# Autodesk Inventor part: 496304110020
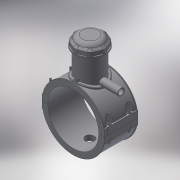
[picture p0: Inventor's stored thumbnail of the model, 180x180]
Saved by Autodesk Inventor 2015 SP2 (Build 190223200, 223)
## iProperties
Created: 2017-07
Part Number: 496304110020
Material: Generic
Description: PLASSON TAPPING SADDLE 110x20
Document SubType Name: Modeling
Designer: KIM
Mass: 688.812 g
Surface Area: 1656.06 cm^2
Volume: 688.812 cm^3
Density: 1 g/cm^3
Appearance: Default
Author: KIM
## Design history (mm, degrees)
derived "496304.ipt"
feature "Solid1::496304.ipt"
feature "Solid2::496304.ipt"
feature "Solid4::496304.ipt"
feature "Solid5::496304.ipt"
tag "TaggingFeature1"
body "Solid1"
body "Solid2"
other parameters: "d2" = 148, "d3" = 27.5, "d4" = 118, "d5" = 0, "d6" = 0.1, "d8" = 0, "d19" = 6, "d20" = 6, "d21" = 70.8, "d23" = 0, "d24" = 35.4, "d26" = 0, "d29" = 3, "d30" = 36.66667, "d31" = 6, "d32" = 0, "d33" = 0, "d34" = 0.6, "d40" = 68.64, "d41" = 66, "d43" = 0, "d45" = 0, "d47" = 136.8, "d70" = 15, "d72" = 0, "d73" = 6, "d75" = 5, "d76" = 0, "d77" = 5.5, "d78" = 85, "d79" = 15, "d80" = 47.2, "d82" = 5 deg, "d84" = 4, "d85" = 14, "d86" = 0, "d87" = 3, "d88" = 0, "d89" = 1, "d90" = 1, "d91" = 94.4, "d92" = 0, "d93" = 0.5, "d94" = 57.89474, "d96" = 134.64, "d97" = 2.36, "d98" = 0, "d102" = 1.1, "d120" = 140 deg, "d121" = 24.228, "d122" = 20 deg, "d123" = 264, "d124" = 79.2, "d126" = 0, "d143" = 113.3, "d145" = 16.92308, "d149" = 1.65, "d150" = 18.61538, "d153" = 118, "d154" = 0, "d156" = 66, "d157" = 160 deg, "d159" = 4.4, "d161" = 1.65, "d162" = 70.8, "d163" = 0, "d164" = 55, "d167" = 11, "d168" = 64.39024, "d170" = 3.375, "d172" = 0, "d173" = 1, "d175" = 55, "d176" = 20 deg, "d177" = 7.7, "d178" = 22, "d180" = 0, "d183" = 8.8, "d184" = 6.16, "d185" = 38.35, "d186" = 38.35, "d187" = 66, "d188" = 6.6, "d189" = 7.7, "d190" = 0, "d191" = 99, "d193" = 6.3, "d194" = 4.13, "d195" = 90 deg, "d197" = 0, "d199" = 0, "d200" = 11, "d202" = 0, "d203" = 114, "d204" = 62.7, "d205" = 46.2, "d206" = 56.1, "d207" = 85.5, "d208" = 88.92, "d209" = 106.02, "d210" = 56.76, "d211" = 66, "d212" = 52.8, "d213" = 5.4, "d216" = 0, "d217" = 11, "d218" = 11, "d219" = 2.2, "d224" = 0, "d230" = 4.4, "d233" = 6, "d236" = 74, "d237" = 35.4, "d238" = 6.02433, "d240" = 35.4, "d241" = 35.4, "d242" = 35.4, "d243" = 6, "d244" = 35.4, "d245" = 35.4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
